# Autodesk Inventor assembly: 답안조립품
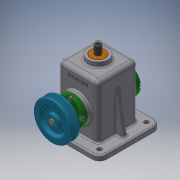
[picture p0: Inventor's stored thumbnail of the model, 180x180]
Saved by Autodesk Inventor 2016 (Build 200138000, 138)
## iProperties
Created: 2022-11
Part Number: 답안조립품
Material: 일반
Document SubType Name: Assembly
Designer: CAD-13
Author: CAD-13
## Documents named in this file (15)
- C:\Users\CAD-13\Desktop\721106V1014\답안조립품.iam
- C:\Users\CAD-13\Desktop\721106V1014\답안본체.ipt
- C:\Users\CAD-13\Desktop\721106V1014\편심축.ipt
- C:\Users\CAD-13\Desktop\721106V1014\베어링 6201.ipt
- C:\Users\CAD-13\Desktop\721106V1014\뒤커버.ipt
- C:\Users\CAD-13\Desktop\721106V1014\링크.ipt
- C:\Users\CAD-13\Desktop\721106V1014\앞커버.ipt
- C:\Users\CAD-13\Desktop\721106V1014\키 4 x 4 x 15.ipt
- C:\Users\CAD-13\Desktop\721106V1014\V벨트풀리.ipt
- C:\Users\CAD-13\Desktop\721106V1014\멈춤나사 M3 x 8.ipt
- C:\Users\CAD-13\Desktop\721106V1014\핀 5 x 18.ipt
- C:\Users\CAD-13\Desktop\721106V1014\고정핀 1.2 x 10.ipt
- C:\Users\CAD-13\Desktop\721106V1014\볼트 M4 x 12.ipt
- C:\Users\CAD-13\Desktop\721106V1014\슬라이드.ipt
- C:\Users\CAD-13\Desktop\721106V1014\부시.ipt
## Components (11 placed, 4 different names)
1. 핀 5 x 18:1
2. 고정핀 1.2 x 10:1
3. V벨트풀리:1
4. ISO 4762 M4 x 12:1
5. ISO 4762 M4 x 12:2
6. ISO 4762 M4 x 12:3
7. ISO 4762 M4 x 12:4
8. ISO 4762 M4 x 12:5
9. ISO 4762 M4 x 12:6
10. ISO 4762 M4 x 12:7
11. ISO 4762 M4 x 12:8
